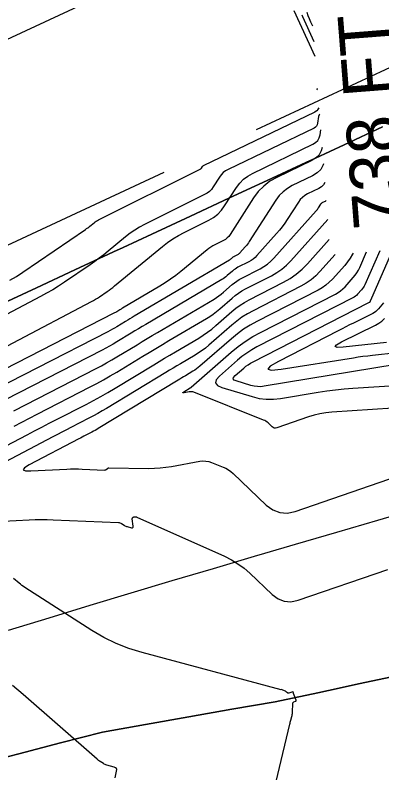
# Model space of a CAD drawing. Extents: x 1354696 to 1366163, y 660729 to 670380.
# Drawn here: x 1361316.8 to 1361360.1, y 664634.7 to 664723.9 of the extents above; entities that cross this region are included whole.
import ezdxf

# ---------------------------------------------------------------- set-up
doc = ezdxf.new("R2010")
doc.units = 0
for name, color, linetype in [('R_Contour Annot', 7, 'Continuous'), ('R_Contours', 7, 'Continuous'), ('R_Erosion', 7, 'Continuous'), ('R_Fin Surface', 7, 'Continuous')]:
    doc.layers.add(name, color=color, linetype=linetype)

msp = doc.modelspace()

# ---------------------------------------------------------------- linework, layer by layer
at = {"layer": 'R_Contours'}
for points in [[(1361352.186, 664719.06), (1361349.708, 664724.462)], [(1361350.609, 664723.997), (1361350.694, 664723.797), (1361352.047, 664720.849)], [(1361351.907, 664722.639), (1361351.681, 664723.132), (1361351.523, 664723.5), (1361351.386, 664723.876), (1361351.27, 664724.258)], [(1361352.491, 664715.157), (1361352.459, 664715.167), (1361352.424, 664715.205), (1361352.437, 664715.256), (1361352.48, 664715.3)], [(1361316.208, 664692.719), (1361316.967, 664693.189), (1361317.712, 664693.681), (1361325.117, 664698.712), (1361325.249, 664698.804), (1361325.378, 664698.899), (1361325.506, 664698.997), (1361325.631, 664699.098), (1361326.128, 664699.507), (1361326.255, 664699.605), (1361326.387, 664699.696), (1361326.523, 664699.779), (1361326.665, 664699.855), (1361338.653, 664705.815), (1361338.696, 664705.84), (1361338.734, 664705.87), (1361338.767, 664705.904), (1361338.797, 664705.944), (1361338.904, 664706.112), (1361338.934, 664706.151), (1361338.967, 664706.186), (1361339.006, 664706.215), (1361339.048, 664706.239), (1361352.188, 664712.568), (1361352.191, 664712.57), (1361352.193, 664712.572), (1361352.194, 664712.575), (1361352.195, 664712.577), (1361352.197, 664712.59), (1361352.198, 664712.593), (1361352.199, 664712.596), (1361352.201, 664712.598), (1361352.204, 664712.599), (1361352.405, 664712.702), (1361352.438, 664712.722), (1361352.467, 664712.745), (1361352.493, 664712.772), (1361352.516, 664712.803), (1361352.658, 664713.02)], [(1361352.714, 664712.293), (1361352.658, 664712.191), (1361352.608, 664712.008), (1361352.482, 664711.222), (1361352.432, 664711.04), (1361352.345, 664710.885), (1361352.221, 664710.757), (1361352.061, 664710.657), (1361341.921, 664705.773), (1361341.622, 664705.604), (1361341.355, 664705.399), (1361341.119, 664705.159), (1361340.915, 664704.883), (1361340.161, 664703.71), (1361339.957, 664703.434), (1361339.722, 664703.192), (1361339.456, 664702.985), (1361339.159, 664702.813), (1361332.072, 664699.289), (1361331.485, 664698.976), (1361330.918, 664698.631), (1361330.372, 664698.255), (1361329.846, 664697.846), (1361327.785, 664696.149), (1361327.265, 664695.731), (1361326.736, 664695.326), (1361326.198, 664694.932), (1361325.65, 664694.551), (1361322.639, 664692.505), (1361321.948, 664692.049), (1361321.244, 664691.612), (1361320.528, 664691.196), (1361319.8, 664690.8), (1361309.761, 664685.514)], [(1361307.321, 664680.475), (1361325.814, 664690.212), (1361326.056, 664690.344), (1361326.294, 664690.483), (1361326.528, 664690.628), (1361326.758, 664690.779), (1361327.67, 664691.399), (1361327.896, 664691.557), (1361328.118, 664691.719), (1361328.337, 664691.887), (1361328.552, 664692.059), (1361334.203, 664696.711), (1361334.802, 664697.176), (1361335.424, 664697.606), (1361336.07, 664697.998), (1361336.739, 664698.355), (1361339.666, 664699.81), (1361340.217, 664700.131), (1361340.71, 664700.515), (1361341.147, 664700.964), (1361341.525, 664701.476), (1361342.926, 664703.655), (1361343.305, 664704.167), (1361343.743, 664704.613), (1361344.239, 664704.993), (1361344.793, 664705.306), (1361351.933, 664708.746), (1361352.252, 664708.945), (1361352.498, 664709.198), (1361352.67, 664709.505), (1361352.769, 664709.867), (1361352.86, 664710.43)], [(1361353.02, 664708.378), (1361352.908, 664707.971), (1361352.65, 664707.51), (1361352.283, 664707.132), (1361351.806, 664706.835), (1361347.665, 664704.84), (1361346.855, 664704.381), (1361346.13, 664703.826), (1361345.491, 664703.175), (1361344.936, 664702.427), (1361342.167, 664698.117), (1361342.004, 664697.898), (1361341.817, 664697.705), (1361341.606, 664697.54), (1361341.369, 664697.403), (1361340.375, 664696.908), (1361340.13, 664696.778), (1361339.895, 664696.635), (1361339.667, 664696.478), (1361339.449, 664696.308), (1361336.349, 664693.757), (1361335.752, 664693.285), (1361335.139, 664692.837), (1361334.508, 664692.414), (1361333.861, 664692.015), (1361329.494, 664689.439), (1361329.408, 664689.389), (1361329.322, 664689.337), (1361329.236, 664689.286), (1361329.151, 664689.234), (1361328.809, 664689.028), (1361328.723, 664688.977), (1361328.636, 664688.927), (1361328.548, 664688.879), (1361328.46, 664688.833), (1361308.374, 664678.554)], [(1361353.172, 664706.432), (1361353.138, 664706.31), (1361352.847, 664705.79), (1361352.433, 664705.363), (1361351.894, 664705.028), (1361349.494, 664703.871), (1361348.924, 664703.548), (1361348.414, 664703.158), (1361347.963, 664702.699), (1361347.573, 664702.172), (1361344.425, 664697.274), (1361344.318, 664697.115), (1361344.206, 664696.961), (1361344.087, 664696.811), (1361343.962, 664696.666), (1361343.318, 664695.947), (1361343.255, 664695.882), (1361343.186, 664695.824), (1361343.113, 664695.773), (1361343.034, 664695.728), (1361342.654, 664695.534), (1361342.602, 664695.505), (1361342.551, 664695.473), (1361342.503, 664695.438), (1361342.457, 664695.4), (1361342.276, 664695.242), (1361342.23, 664695.203), (1361342.182, 664695.167), (1361342.133, 664695.133), (1361342.082, 664695.102), (1361330.858, 664688.483), (1361330.601, 664688.33), (1361330.344, 664688.177), (1361330.087, 664688.024), (1361329.831, 664687.869), (1361328.808, 664687.25), (1361328.551, 664687.097), (1361328.291, 664686.95), (1361328.029, 664686.806), (1361327.764, 664686.668), (1361311.137, 664678.159)], [(1361353.342, 664704.255), (1361353.181, 664703.968), (1361352.949, 664703.728), (1361352.647, 664703.54), (1361351.3, 664702.892), (1361350.981, 664702.711), (1361350.695, 664702.491), (1361350.442, 664702.234), (1361350.223, 664701.939), (1361348.913, 664699.9), (1361348.619, 664699.462), (1361348.308, 664699.037), (1361347.981, 664698.624), (1361347.637, 664698.224), (1361345.324, 664695.641), (1361345.112, 664695.424), (1361344.882, 664695.23), (1361344.636, 664695.058), (1361344.372, 664694.907), (1361343.097, 664694.256), (1361342.922, 664694.159), (1361342.753, 664694.052), (1361342.591, 664693.935), (1361342.436, 664693.807), (1361341.829, 664693.278), (1361341.675, 664693.149), (1361341.515, 664693.028), (1361341.35, 664692.914), (1361341.179, 664692.808), (1361332.222, 664687.526), (1361331.794, 664687.272), (1361331.366, 664687.017), (1361330.938, 664686.761), (1361330.512, 664686.504), (1361328.807, 664685.472), (1361328.379, 664685.218), (1361327.946, 664684.972), (1361327.509, 664684.733), (1361327.068, 664684.502), (1361313.9, 664677.764)], [(1361316.663, 664677.369), (1361326.371, 664682.337), (1361326.989, 664682.66), (1361327.601, 664682.994), (1361328.206, 664683.339), (1361328.806, 664683.695), (1361331.192, 664685.139), (1361331.789, 664685.499), (1361332.388, 664685.857), (1361332.987, 664686.214), (1361333.587, 664686.569), (1361340.276, 664690.514), (1361340.566, 664690.695), (1361340.848, 664690.888), (1361341.12, 664691.094), (1361341.382, 664691.313), (1361342.415, 664692.215), (1361342.679, 664692.432), (1361342.954, 664692.631), (1361343.242, 664692.813), (1361343.541, 664692.978), (1361345.71, 664694.087), (1361346.159, 664694.343), (1361346.578, 664694.636), (1361346.969, 664694.967), (1361347.331, 664695.336), (1361352.313, 664700.9), (1361352.387, 664700.987), (1361352.458, 664701.076), (1361352.526, 664701.169), (1361352.589, 664701.264), (1361352.873, 664701.706), (1361352.921, 664701.77), (1361352.976, 664701.825), (1361353.038, 664701.873), (1361353.107, 664701.912), (1361353.399, 664702.053), (1361353.464, 664702.094), (1361353.507, 664702.137)], [(1361316.683, 664675.556), (1361317.596, 664676.031), (1361318.511, 664676.504), (1361319.426, 664676.974), (1361325.675, 664680.172), (1361326.469, 664680.587), (1361327.256, 664681.017), (1361328.034, 664681.46), (1361328.805, 664681.917), (1361331.873, 664683.774), (1361332.64, 664684.237), (1361333.409, 664684.697), (1361334.18, 664685.156), (1361334.951, 664685.613), (1361339.373, 664688.22), (1361339.783, 664688.475), (1361340.18, 664688.748), (1361340.565, 664689.04), (1361340.936, 664689.349), (1361342.394, 664690.622), (1361342.766, 664690.929), (1361343.156, 664691.21), (1361343.562, 664691.467), (1361343.984, 664691.7), (1361347.048, 664693.266), (1361347.682, 664693.627), (1361348.274, 664694.042), (1361348.826, 664694.509), (1361349.337, 664695.03), (1361353.683, 664699.884)], [(1361313.328, 664671.954), (1361318.233, 664674.531), (1361319.099, 664674.984), (1361319.967, 664675.436), (1361320.836, 664675.885), (1361321.706, 664676.332), (1361325.188, 664678.114), (1361326.055, 664678.567), (1361326.913, 664679.035), (1361327.762, 664679.519), (1361328.603, 664680.018), (1361333.157, 664682.774), (1361333.793, 664683.157), (1361334.43, 664683.539), (1361335.068, 664683.919), (1361335.708, 664684.298), (1361338.47, 664685.926), (1361339, 664686.256), (1361339.513, 664686.609), (1361340.01, 664686.985), (1361340.489, 664687.385), (1361342.373, 664689.03), (1361342.854, 664689.426), (1361343.357, 664689.789), (1361343.882, 664690.122), (1361344.428, 664690.422), (1361348.466, 664692.487), (1361349.246, 664692.931), (1361349.976, 664693.441), (1361350.655, 664694.017), (1361351.283, 664694.658), (1361353.866, 664697.542)], [(1361354.558, 664695.769), (1361352.761, 664693.763), (1361352.259, 664693.25), (1361351.716, 664692.79), (1361351.132, 664692.382), (1361350.509, 664692.027), (1361344.871, 664689.144), (1361344.202, 664688.776), (1361343.559, 664688.369), (1361342.942, 664687.923), (1361342.352, 664687.438), (1361339.639, 664685.068), (1361339.257, 664684.749), (1361338.861, 664684.449), (1361338.451, 664684.167), (1361338.028, 664683.905), (1361336.309, 664682.891), (1361335.879, 664682.637), (1361335.451, 664682.381), (1361335.023, 664682.125), (1361334.595, 664681.867), (1361327.61, 664677.639), (1361327.096, 664677.335), (1361326.578, 664677.04), (1361326.054, 664676.754), (1361325.525, 664676.477), (1361323.398, 664675.389), (1361322.867, 664675.116), (1361322.337, 664674.842), (1361321.807, 664674.566), (1361321.278, 664674.289), (1361314.233, 664670.588)], [(1361356.677, 664695.935), (1361356.61, 664695.797), (1361356.337, 664695.336), (1361356.029, 664694.898), (1361355.686, 664694.482), (1361354.24, 664692.867), (1361353.863, 664692.483), (1361353.456, 664692.138), (1361353.019, 664691.833), (1361352.551, 664691.566), (1361345.315, 664687.866), (1361344.522, 664687.43), (1361343.76, 664686.948), (1361343.03, 664686.419), (1361342.331, 664685.845), (1361338.612, 664682.597), (1361338.417, 664682.434), (1361338.214, 664682.28), (1361338.005, 664682.136), (1361337.789, 664682.002), (1361336.91, 664681.484), (1361336.69, 664681.354), (1361336.471, 664681.223), (1361336.252, 664681.092), (1361336.034, 664680.961), (1361326.617, 664675.261), (1361326.431, 664675.151), (1361326.243, 664675.044), (1361326.053, 664674.94), (1361325.861, 664674.84), (1361325.091, 664674.446), (1361324.899, 664674.347), (1361324.706, 664674.248), (1361324.515, 664674.148), (1361324.323, 664674.048), (1361318.485, 664670.981), (1361317.928, 664670.637), (1361317.775, 664670.404), (1361318.025, 664670.282), (1361318.68, 664670.27), (1361322.9, 664670.485), (1361323.359, 664670.503), (1361323.819, 664670.511), (1361324.278, 664670.507), (1361324.738, 664670.493), (1361327.401, 664670.38), (1361327.446, 664670.382), (1361327.488, 664670.393), (1361327.528, 664670.412), (1361327.564, 664670.44), (1361327.702, 664670.568), (1361327.738, 664670.596), (1361327.777, 664670.616), (1361327.819, 664670.627), (1361327.865, 664670.631), (1361332.561, 664670.576), (1361333.243, 664670.584), (1361333.923, 664670.625), (1361334.599, 664670.698), (1361335.273, 664670.804), (1361338.595, 664671.406), (1361338.949, 664671.446), (1361339.298, 664671.436), (1361339.643, 664671.376), (1361339.982, 664671.267), (1361341.329, 664670.731), (1361341.657, 664670.582), (1361341.966, 664670.405), (1361342.256, 664670.198), (1361342.528, 664669.963), (1361346.43, 664666.251), (1361347.196, 664665.678), (1361348.019, 664665.363), (1361348.897, 664665.307), (1361349.833, 664665.508), (1361371.927, 664673.091)], [(1361370.957, 664678.305), (1361354.167, 664677.184), (1361353.461, 664677.113), (1361352.765, 664676.997), (1361352.077, 664676.835), (1361351.399, 664676.627), (1361347.667, 664675.346), (1361347.517, 664675.314), (1361347.376, 664675.323), (1361347.243, 664675.373), (1361347.12, 664675.465), (1361346.645, 664675.917), (1361346.522, 664676.024), (1361346.391, 664676.117), (1361346.251, 664676.197), (1361346.103, 664676.264), (1361337.893, 664679.532), (1361337.754, 664679.577), (1361337.612, 664679.601), (1361337.468, 664679.605), (1361337.322, 664679.589), (1361336.734, 664679.482), (1361336.621, 664679.469), (1361336.577, 664679.481), (1361336.602, 664679.519), (1361336.695, 664679.584), (1361337.473, 664680.054), (1361337.492, 664680.066), (1361337.511, 664680.077), (1361337.549, 664680.1), (1361337.559, 664680.106), (1361337.568, 664680.112), (1361337.577, 664680.119), (1361337.585, 664680.126), (1361342.31, 664684.253), (1361343.118, 664684.916), (1361343.962, 664685.527), (1361344.842, 664686.084), (1361345.758, 664686.589), (1361354.594, 664691.106), (1361354.905, 664691.284), (1361355.196, 664691.487), (1361355.467, 664691.716), (1361355.718, 664691.972), (1361356.68, 664693.047), (1361356.909, 664693.323), (1361357.114, 664693.615), (1361357.295, 664693.922), (1361357.452, 664694.244), (1361358.252, 664696.058)], [(1361359.811, 664696.179), (1361358.058, 664692.206), (1361357.98, 664692.046), (1361357.89, 664691.894), (1361357.788, 664691.749), (1361357.674, 664691.611), (1361357.196, 664691.077), (1361357.071, 664690.95), (1361356.937, 664690.836), (1361356.792, 664690.734), (1361356.637, 664690.646), (1361345.335, 664684.867), (1361344.72, 664684.529), (1361344.13, 664684.155), (1361343.564, 664683.746), (1361343.022, 664683.301), (1361340.902, 664681.449), (1361340.523, 664681.018), (1361340.444, 664680.652), (1361340.666, 664680.35), (1361341.188, 664680.112), (1361344.774, 664679.018), (1361345.599, 664678.816), (1361346.43, 664678.711), (1361347.268, 664678.705), (1361348.113, 664678.797), (1361352.543, 664679.533), (1361353.565, 664679.69), (1361354.591, 664679.822), (1361355.619, 664679.929), (1361356.65, 664680.01), (1361364.699, 664680.548)], [(1361361.755, 664682.823), (1361346.191, 664680.237), (1361345.79, 664680.194), (1361345.391, 664680.196), (1361344.995, 664680.246), (1361344.603, 664680.342), (1361342.897, 664680.863), (1361342.649, 664680.976), (1361342.543, 664681.12), (1361342.58, 664681.294), (1361342.761, 664681.499), (1361343.769, 664682.38), (1361344.027, 664682.592), (1361344.297, 664682.786), (1361344.577, 664682.964), (1361344.87, 664683.125), (1361358.452, 664690.07), (1361358.522, 664690.105), (1361358.622, 664690.157), (1361358.636, 664690.164), (1361358.661, 664690.176), (1361358.665, 664690.179), (1361358.669, 664690.182), (1361358.677, 664690.192), (1361358.679, 664690.196), (1361358.68, 664690.199), (1361358.722, 664690.298), (1361358.73, 664690.316), (1361358.737, 664690.333), (1361358.745, 664690.35), (1361358.752, 664690.368), (1361361.37, 664696.301)], [(1361360.262, 664690.083), (1361359.681, 664689.371), (1361359.528, 664689.202), (1361359.36, 664689.053), (1361359.177, 664688.922), (1361358.979, 664688.81), (1361356.706, 664687.682), (1361356.259, 664687.459), (1361355.812, 664687.235), (1361355.367, 664687.009), (1361354.922, 664686.782), (1361347.882, 664683.17), (1361346.91, 664682.605), (1361346.634, 664682.268), (1361347.056, 664682.157), (1361348.174, 664682.273), (1361356.717, 664683.61), (1361357.275, 664683.694), (1361357.833, 664683.771), (1361358.392, 664683.84), (1361358.953, 664683.903), (1361361.819, 664684.206)], [(1361360.594, 664685.397), (1361355.483, 664684.857), (1361354.805, 664684.824), (1361354.549, 664684.915), (1361354.716, 664685.128), (1361355.306, 664685.464), (1361359.296, 664687.444), (1361359.691, 664687.667), (1361360.055, 664687.927), (1361360.389, 664688.224)], [(1361315.401, 664664.355), (1361318.488, 664664.512), (1361319.187, 664664.54), (1361319.885, 664664.551), (1361320.584, 664664.546), (1361321.284, 664664.524), (1361328.99, 664664.198), (1361329.086, 664664.187), (1361329.179, 664664.165), (1361329.267, 664664.13), (1361329.352, 664664.084), (1361329.683, 664663.872), (1361329.767, 664663.823), (1361329.854, 664663.78), (1361329.944, 664663.745), (1361330.038, 664663.716), (1361330.54, 664663.581), (1361330.639, 664663.569), (1361330.705, 664663.594), (1361330.738, 664663.656), (1361330.738, 664663.756), (1361330.619, 664664.625), (1361330.618, 664664.655), (1361330.624, 664664.683), (1361330.637, 664664.708), (1361330.657, 664664.731), (1361330.749, 664664.817), (1361330.773, 664664.836), (1361330.8, 664664.849), (1361330.828, 664664.857), (1361330.859, 664664.859), (1361331.033, 664664.857), (1361331.072, 664664.855), (1361331.11, 664664.848), (1361331.148, 664664.838), (1361331.184, 664664.824), (1361341.51, 664660.22), (1361342.32, 664659.817), (1361343.088, 664659.35), (1361343.813, 664658.818), (1361344.494, 664658.222), (1361347.135, 664655.711), (1361347.82, 664655.198), (1361348.555, 664654.917), (1361349.342, 664654.866), (1361350.178, 664655.046), (1361360.748, 664658.674)], [(1361345.163, 664623.472), (1361349.21, 664640.458), (1361349.238, 664640.571), (1361349.266, 664640.684), (1361349.295, 664640.797), (1361349.325, 664640.909), (1361349.445, 664641.358), (1361349.473, 664641.471), (1361349.494, 664641.585), (1361349.509, 664641.7), (1361349.518, 664641.816), (1361349.575, 664642.936), (1361349.584, 664642.984), (1361349.604, 664643.024), (1361349.636, 664643.055), (1361349.679, 664643.078), (1361349.876, 664643.154), (1361349.917, 664643.176), (1361349.941, 664643.207), (1361349.948, 664643.245), (1361349.938, 664643.29), (1361349.655, 664644.045), (1361349.648, 664644.067), (1361349.641, 664644.089), (1361349.636, 664644.111), (1361349.632, 664644.134), (1361349.619, 664644.225), (1361349.613, 664644.244), (1361349.603, 664644.256), (1361349.588, 664644.26), (1361349.568, 664644.256), (1361349.083, 664644.089), (1361349.044, 664644.081), (1361349.008, 664644.083), (1361348.974, 664644.096), (1361348.943, 664644.12), (1361348.821, 664644.235), (1361348.79, 664644.263), (1361348.757, 664644.287), (1361348.721, 664644.309), (1361348.684, 664644.327), (1361348.197, 664644.544), (1361348.19, 664644.546), (1361348.185, 664644.545), (1361348.183, 664644.541), (1361348.183, 664644.534), (1361348.188, 664644.497), (1361348.188, 664644.489), (1361348.185, 664644.485), (1361348.18, 664644.483), (1361348.173, 664644.484), (1361331.791, 664648.878), (1361330.236, 664649.359), (1361328.731, 664649.954), (1361327.277, 664650.664), (1361325.873, 664651.488), (1361317.962, 664656.543), (1361317.785, 664656.661), (1361317.612, 664656.786), (1361317.444, 664656.917), (1361317.281, 664657.055), (1361316.638, 664657.618)], [(1361328.599, 664634.131), (1361328.788, 664634.924), (1361328.803, 664635.092), (1361328.762, 664635.225), (1361328.664, 664635.325), (1361328.51, 664635.391), (1361327.629, 664635.627), (1361327.523, 664635.66), (1361327.42, 664635.701), (1361327.321, 664635.749), (1361327.225, 664635.805), (1361326.848, 664636.046), (1361326.755, 664636.108), (1361326.665, 664636.173), (1361326.577, 664636.241), (1361326.492, 664636.313), (1361317.776, 664643.941), (1361316.486, 664645.011)]]:
    msp.add_lwpolyline(points, dxfattribs=at)
at = {"layer": 'R_Erosion'}
for points in [[(1361314.804, 664689.743), (1361319.339, 664691.848), (1361323.874, 664693.954), (1361328.4, 664696.055), (1361328.409, 664696.059), (1361329.543, 664696.586), (1361332.944, 664698.165), (1361337.479, 664700.27), (1361342.014, 664702.376), (1361344.128, 664703.357), (1361346.549, 664704.481), (1361351.084, 664706.587), (1361352.227, 664707.118), (1361355.619, 664708.692), (1361360.154, 664710.798)], [(1361360.154, 664710.798), (1361355.619, 664708.692), (1361352.227, 664707.118), (1361351.084, 664706.587), (1361346.549, 664704.481), (1361344.128, 664703.357), (1361342.014, 664702.376), (1361337.479, 664700.27), (1361332.944, 664698.165), (1361329.543, 664696.586), (1361328.409, 664696.059), (1361328.4, 664696.055), (1361323.874, 664693.954), (1361319.339, 664691.848), (1361314.804, 664689.743)], [(1361381.397, 664649.854), (1361378.977, 664649.502), (1361377.692, 664649.275), (1361372.599, 664648.372), (1361369.881, 664647.886), (1361367.543, 664647.388), (1361362.529, 664646.314), (1361357.519, 664645.232), (1361353.764, 664644.414), (1361352.513, 664644.141), (1361352.503, 664644.139), (1361347.486, 664643.097), (1361342.382, 664642.216), (1361337.282, 664641.327), (1361332.187, 664640.428), (1361327.106, 664639.497), (1361322.164, 664638.268), (1361317.26, 664636.957), (1361312.327, 664635.709)], [(1361312.327, 664635.709), (1361317.26, 664636.957), (1361322.164, 664638.268), (1361327.106, 664639.497), (1361332.187, 664640.428), (1361337.282, 664641.327), (1361342.382, 664642.216), (1361347.486, 664643.097), (1361352.503, 664644.139), (1361352.513, 664644.141), (1361353.764, 664644.414), (1361357.519, 664645.232), (1361362.529, 664646.314), (1361367.543, 664647.388), (1361369.881, 664647.886), (1361372.599, 664648.372), (1361377.692, 664649.275), (1361378.977, 664649.502), (1361381.397, 664649.854)], [(1361362.536, 664646.301), (1361357.526, 664645.219), (1361353.771, 664644.401), (1361352.519, 664644.128), (1361352.509, 664644.126), (1361347.492, 664643.084), (1361342.388, 664642.203), (1361337.288, 664641.314), (1361332.193, 664640.415), (1361327.112, 664639.484), (1361322.17, 664638.255), (1361317.266, 664636.945), (1361312.333, 664635.696)]]:
    msp.add_lwpolyline(points, dxfattribs=at)
at = {"layer": 'R_Fin Surface'}
for p, q in [((1361293.918, 664710.917), (1361337.455, 664731.13)), ((1361345.265, 664710.5), (1361388.802, 664730.713)), ((1361290.844, 664685.234), (1361334.381, 664705.447))]:
    msp.add_line(p, q, dxfattribs=at)
msp.add_lwpolyline([(1361316.02, 664651.503), (1361320.847, 664652.979), (1361325.678, 664654.446), (1361330.513, 664655.906), (1361335.352, 664657.357), (1361340.195, 664658.8), (1361345.032, 664660.231), (1361345.042, 664660.234), (1361346.254, 664660.591), (1361349.892, 664661.66), (1361354.747, 664663.078), (1361359.605, 664664.487), (1361361.87, 664665.141)], dxfattribs=at)

# ---------------------------------------------------------------- texts
at = {"layer": 'R_Contour Annot'}
msp.add_text('738 FT', height=6, rotation=94.46282, dxfattribs=at).set_placement((1361362.78, 664698.994))

doc.saveas('drawing.dxf')
